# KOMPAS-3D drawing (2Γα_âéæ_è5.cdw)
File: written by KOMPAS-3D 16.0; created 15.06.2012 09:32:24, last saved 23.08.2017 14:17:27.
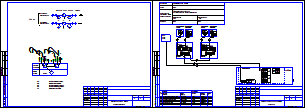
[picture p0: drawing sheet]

Sheets 1-2: A3, landscape

Title block, sheet 1: name: г. Москва, ул. Нежинская, д. 14, к.8 (кв. 1 и кв. 2); sheet number: 1; sheets: 27 / 28; sheet format: A3; stored path: D:\Проекты\Лыткарино\ул. Квартал 3А, д.25\710.74 РП.cdw; cell 320: Р
Title block, sheet 2: sheet number: 2

Views: Вид 2, Вид 3, Вид 4, Вид 5
Referenced files in C:\Program Files (x86)\ASCON\KOMPAS-3D V16\Sys\: spds.lcs, EngSys.lcs, GRAPHIC.LHS
Referenced files: graphic.tdp
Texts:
  МО, Клинский район, д. Решетниково, ул. Центральная, д.14
  GOST Common
  Normal
  List Paragraph
  heading 3
  для схемы
  txt
  краны
  Фоновая заливка
  Т0-элементы
  ВРУ
  Плата подключений
  СБ МКТС
  Pt 100
  Преобразователь
  температуры
  давления
  UP+
  UP-
  ИМП
  Лин
  Измерительный
  модуль М121
  каб.
  Начало
  трассы
  Трассы
  Марка
  Проложен
  Датчик температуры (Т3)
  Датчик температуры (Т4)
  Датчик давления (Т3)
  Датчик давления (Т4)
  Изм. модуль (Т4)
  Изм. модуль (Т3)
  ВРУ 220В, 50 Гц
  ИМ1 УУТЭ
  ИМ2 УУТЭ
  ИМ (Т3)
  FTP
  ПВС
  Конец
  Кол-во и
  сеч. жил
  Длина,
  Агрегат
  Системный блок  МКТС
  Среда
  Вода
  параметра и место
  отбора импульса
  Учет тепловой энергии и
  расхода горячей воды системы ГВС
  Подающий
  трубопровод
  ГВС
  Обратный
  ИМ1
  ИМ2
  приборы
  по месту
  шкаф
  учета
  UQIES
  УУГВС
  Функциональная схема
  Преобразователь расхода
  Термопреобразователь
  Преобразователь давления
  Преобразователь цифровой
  Системный блок МКТС
  Размеры, параметризация
  сит. план
  подача ГВС
  обратка ГВС
  хвс
  обратка
  POLYLINE_STYLE_0.25_RGB_0_0_0
  стены
  Основная (не является границей для штриховки)
  POLYLINE_STYLE_0.18_RGB_0_0_0
  ХВС
  зеленая
  Красная тонкая
  арматура
  Подача
  Скрытая линия
  Ось Z
  Ось Y
  Ось X
  Образующая трубопровода (проектируемого)
  Трубопровод толщиной 0.6мм (одна линия)
  Трубопровод толщиной 1.2мм (одна линия)
  Трубопровод толщиной 1.0мм (одна линия)
  Трубопровод толщиной 0.8мм (одна линия)
  Трубопровод существующий (одна линия)
  Трубопровод невидимый (одна линия)
  Трубопровод демонтируемый (одна линия)
  Осевая трубопровода
  Осевая трубопровода (демонтируемого)
  Образующая трубопровода (существующего)
  Образующая трубопровода (невидимого)
  Изолированный трубопровод проектируемый (одна линия)
  Изолированный трубопровод существующий (одна линия)
  Образующая изоляции
  Изоляция
  Изолированный трубопровод невидимый (одна линия)
  Штрих пвс 075
  штрих пвс 2,5
  существующее оборудование
  Существующее оборудование
  K5LT_BASIC_RGB_0_0_255_THICK_0.53
  POLYLINE_STYLE_1.51_RGB_0_0_255
  POLYLINE_STYLE_0.50_RGB_128_128_128
  K5LT_AXLED_RGB_255_128_0_SC_1_THICK_0.18
  ACAD_ISO04W100_RGB_0_0_0_SC_1_THICK_0.18
  тонкая черная
  пломбировка
  Провода
  синий штрих
  Стили документа
  G2co
  расход вторичной воды объемный
  расход вторичной воды объемный при 70гр
  Gco
  расход теплоносителя массовый
  расход теплоносит объемн подающ
  расход теплоносит объемн обр
  Лапир
  Ghvs
  Im1
  Im2
  Im3
  Im4
  Im5
  Khvs
  норматив ХВС
  число подъездов
  число этажей
  Nkv
  число квартир
  тепловая нагрузка на отопление
  сумма Q
  Qgvs
  тепловая нагрузка ГВС
  тепловая нагрузка на циркуляцию ГВС
  иммитовставка или под манометр
  ro1
  ro2
  ro3
  ro4
  верх предел темп граф
  нижн предел темп граф
  темп подачи ГВС
  темп обр ГВС
  темр хол воды
  vzdh
  Kchn
  Ktp
  Knp
  beta
  tnv
  Vклап
  KLP
  RPD
  RDS
  PUMP
  ro5
  Переход К-76 x 3-38 x 2-09Г2С ГОСТ 17378-2001
  Переход ГОСТ 17378-2001
  Переход
  ГОСТ
  Сталь 09Г2С ГОСТ 19281-89
  Переход К-76 x 3-45 x 2,5-09Г2С ГОСТ 17378-2001
  Переход К-57 x 3-38 x 2-09Г2С ГОСТ 17378-2001
  Переход К-57 x 3-32 x 2-09Г2С ГОСТ 17378-2001
  Втулка 20x50
  Переход К-108 x 4-57 x 3-09Г2С ГОСТ 17378-2001
  Переход К-45 x 2,5-32 x 2-09Г2С ГОСТ 17378-2001
  Переход К-89 x 3,5-45 x 2,5-09Г2С ГОСТ 17378-2001
  Переход К-133 x 5-108 x 4-09Г2С ГОСТ 17378-2001
  Переход К-159 x 4,5-89 x 3,5-09Г2С ГОСТ 17378-2001
  Переход К-45 x 2,5-38 x 2-09Г2С ГОСТ 17378-2001
  Фланец 1-32-1 Ст3сп ГОСТ 12820-80
  Фланцы
  Фланец
  квадратный
  Ст3сп
  Ст3сп ГОСТ 380-2005
  Переход К-57 x 3-45 x 2,5-09Г2С ГОСТ 17378-2001
  Переход К-76 x 3-57 x 3-09Г2С ГОСТ 17378-2001
  Фланец 1-50-16 Ст3сп ГОСТ 12821-80
  Переход К-89 x 3,5-76 x 3,5-09Г2С ГОСТ 17378-2001
  Переход К-108 x 4-89 x 3,5-09Г2С ГОСТ 17378-2001
  Тройник 159 x 4,5-09Г2С ГОСТ 17376-2001
  Тройники ГОСТ 17376-2001
  Тройник
  Отвод 90-159 x 4-09Г2С ГОСТ 17375-2001
  Отвод ГОСТ 17375-2001
  Отвод
  Переход К-108 x 4-76 x 3,5-09Г2С ГОСТ 17378-2001
  Переход К-159 x 4,5-108 x 4-09Г2С ГОСТ 17378-2001
  Переход К-133 x 5-76 x 3,5-09Г2С ГОСТ 17378-2001
  Переход К-133 x 4-89 x 3,5-09Г2С ГОСТ 17378-2001
  Переход К-1-42,4 x 2,6-21,3 x 2-TS10 ГОСТ 17378-2001
  TS10
  Сталь TS10 ИСО 2604/2-75
  Фланец 1-20-16 Ст3сп ГОСТ 12820-80
  Лит-Масса-Масштаб
  Материал-Предприятие
  Title Specification
  Body Specification ( left align )
  Body Specificaton ( centered )
  Поз.
  Кол.
  Приме-
  чание
  Таблица спецификации
  Засыпка
  Штрих3
  Штрих2
  Штрих1
  Песок
  Штр0.5пр7
  Штр0.5пр12
  Штр0.3пр10
  Штр1.4пр21.21
  Штр1пр15
  Штр2.12пр35
  Штр1.5пр25
  Штр2.82пр42.42
  Штр2пр30
  SACNCR_ISO 1
  Электрощитовая
  Пр-1
  Ок-1
  вапвыапвы
  Обозначение стандарта
  Типоразмер
  Разраб.
  Пров.
  Т.контр.
  Н.контр.
  Утв.
  автоматизации
  Рабочие чертежи основного комплекта. ГОСТ Р 21.1101-2009 Ф3
  Стадия
  Лист
  Листов
  Изм.
  Кол.уч.
  №док.
  Подп.
  Дата
  Изменение
  Номер документа
  Подпись
  Наименование объекта строительства, в состав которого входит здание, наим. микр
  Наименование здания (сооружения)
  Порядковый номер листа
  Количество листов в документе
  Наименование изображения
  Индекс предприятия, выпускающего документ
  Инв. № подл.
  Подп. и дата
  Взам. инв. №
  Инвентарный номер подлинника
  Подпись принявшего подлинник на хранение
  Инвентарный номер подлинника, взамен которого выпущен данный подлинник
  Согласовано
  Формат листа
  Согласование
  03 Рабочие чертежи основного комплекта. ГОСТ Р 21.1101-2009 Ф3
  Схема соединений внешних
  проводок
Dimensions and other numbers on the sheet: 0; 220В; 50Гц; 1; 2; 3; 6; 5; 4; 4-20; 2x2x0,52; 3х0,75; 15; 25; 9; 7; 8; 60; 4,0; 0,7862; 0,0060; 0,4088; 3,0; 50; 1,2; 3,4; 5,6; 7,8; 10; 09Г2С; 12; 16; 17; 19; 20; 21; 22; 23; 24; 26; 30; 31; 33; 34; 52; 64; 65; 66; 67; 69; 70; 71; 72; 73; 74; 75; 27; 28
